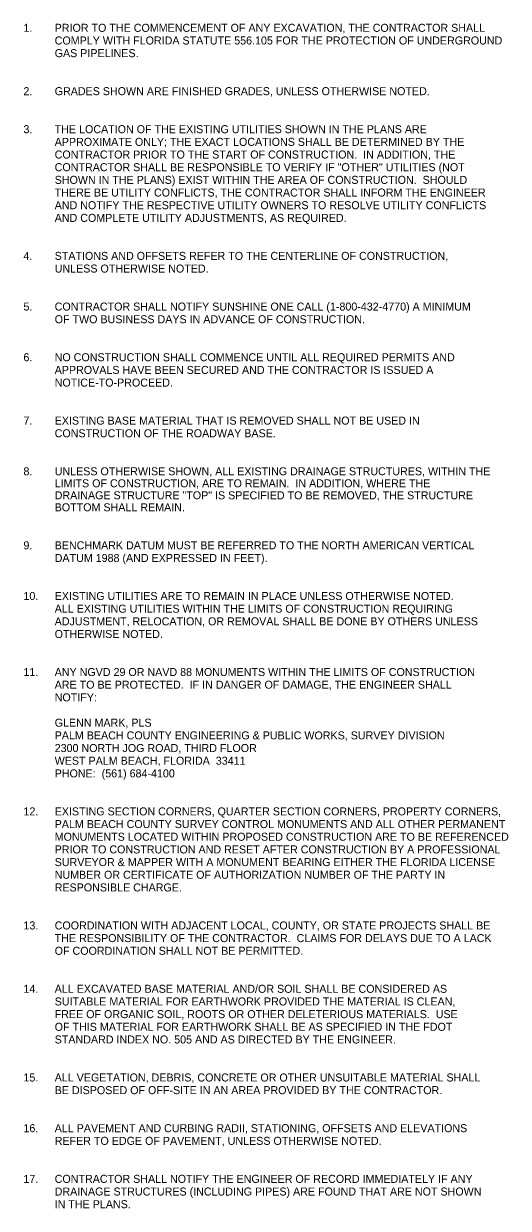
# Model space of a CAD drawing. Extents: x 783907 to 784590, y 832310 to 832609.
# Drawn here: x 784194.4 to 784230.7, y 832519 to 832607.8 of the extents above; entities that cross this region are included whole.
import ezdxf

# ---------------------------------------------------------------- set-up
doc = ezdxf.new("R2010")
doc.units = 0
doc.layers.add('Default', color=7, linetype='Continuous')

msp = doc.modelspace()

# ---------------------------------------------------------------- texts
at = {"layer": 'Default'}
for s, p in [('1.', (784194.352, 832607.22)), ('PRIOR TO THE COMMENCEMENT OF ANY EXCAVATION, THE CONTRACTOR SHALL ', (784196.695, 832607.22)), ('COMPLY WITH FLORIDA STATUTE 556.105 FOR THE PROTECTION OF UNDERGROUND', (784196.695, 832606.27)), ('GAS PIPELINES.', (784196.695, 832605.32)), ('2.', (784194.352, 832602.47)), ('GRADES SHOWN ARE FINISHED GRADES, UNLESS OTHERWISE NOTED.', (784196.695, 832602.47)), ('3.', (784194.352, 832599.62)), ('THE LOCATION OF THE EXISTING UTILITIES SHOWN IN THE PLANS ARE', (784196.695, 832599.62)), ('APPROXIMATE ONLY; THE EXACT LOCATIONS SHALL BE DETERMINED BY THE', (784196.695, 832598.67)), ('CONTRACTOR PRIOR TO THE START OF CONSTRUCTION.  IN ADDITION, THE', (784196.695, 832597.72)), ('CONTRACTOR SHALL BE RESPONSIBLE TO VERIFY IF "OTHER" UTILITIES (NOT', (784196.695, 832596.77)), ('SHOWN IN THE PLANS) EXIST WITHIN THE AREA OF CONSTRUCTION.  SHOULD', (784196.695, 832595.82)), ('THERE BE UTILITY CONFLICTS, THE CONTRACTOR SHALL INFORM THE ENGINEER', (784196.695, 832594.87)), ('AND NOTIFY THE RESPECTIVE UTILITY OWNERS TO RESOLVE UTILITY CONFLICTS', (784196.695, 832593.92)), ('AND COMPLETE UTILITY ADJUSTMENTS, AS REQUIRED.', (784196.695, 832592.97)), ('4.', (784194.352, 832590.12)), ('STATIONS AND OFFSETS REFER TO THE CENTERLINE OF CONSTRUCTION,', (784196.695, 832590.12)), ('UNLESS OTHERWISE NOTED.', (784196.695, 832589.17)), ('5.', (784194.352, 832586.32)), ('CONTRACTOR SHALL NOTIFY SUNSHINE ONE CALL (1-800-432-4770) A MINIMUM', (784196.695, 832586.32)), ('OF TWO BUSINESS DAYS IN ADVANCE OF CONSTRUCTION.', (784196.695, 832585.37)), ('6.', (784194.352, 832582.52)), ('NO CONSTRUCTION SHALL COMMENCE UNTIL ALL REQUIRED PERMITS AND ', (784196.695, 832582.52)), ('APPROVALS HAVE BEEN SECURED AND THE CONTRACTOR IS ISSUED A', (784196.695, 832581.57)), ('NOTICE-TO-PROCEED.', (784196.695, 832580.62)), ('7.', (784194.352, 832577.77)), ('EXISTING BASE MATERIAL THAT IS REMOVED SHALL NOT BE USED IN', (784196.695, 832577.77)), ('CONSTRUCTION OF THE ROADWAY BASE.', (784196.695, 832576.82)), ('8.', (784194.352, 832573.97)), ('UNLESS OTHERWISE SHOWN, ALL EXISTING DRAINAGE STRUCTURES, WITHIN THE', (784196.695, 832573.97)), ('LIMITS OF CONSTRUCTION, ARE TO REMAIN.  IN ADDITION, WHERE THE', (784196.695, 832573.07)), ('DRAINAGE STRUCTURE "TOP" IS SPECIFIED TO BE REMOVED, THE STRUCTURE', (784196.695, 832572.17)), ('BOTTOM SHALL REMAIN.', (784196.695, 832571.27)), ('9.', (784194.352, 832568.42)), ('BENCHMARK DATUM MUST BE REFERRED TO THE NORTH AMERICAN VERTICAL', (784196.695, 832568.42)), ('DATUM 1988 (AND EXPRESSED IN FEET).', (784196.695, 832567.47)), ('10.', (784194.352, 832564.62)), ('EXISTING UTILITIES ARE TO REMAIN IN PLACE UNLESS OTHERWISE NOTED.  ', (784196.695, 832564.62)), ('ALL EXISTING UTILITIES WITHIN THE LIMITS OF CONSTRUCTION REQUIRING', (784196.695, 832563.67)), ('ADJUSTMENT, RELOCATION, OR REMOVAL SHALL BE DONE BY OTHERS UNLESS', (784196.695, 832562.72)), ('OTHERWISE NOTED.', (784196.695, 832561.77)), ('11.', (784194.352, 832558.92)), ('ANY NGVD 29 OR NAVD 88 MONUMENTS WITHIN THE LIMITS OF CONSTRUCTION ', (784196.695, 832558.92)), ('ARE TO BE PROTECTED.  IF IN DANGER OF DAMAGE, THE ENGINEER SHALL ', (784196.695, 832557.97)), ('NOTIFY:', (784196.695, 832557.02)), ('GLENN MARK, PLS', (784196.695, 832555.12)), ('PALM BEACH COUNTY ENGINEERING & PUBLIC WORKS, SURVEY DIVISION', (784196.695, 832554.17)), ('2300 NORTH JOG ROAD, THIRD FLOOR ', (784196.695, 832553.22)), ('WEST PALM BEACH, FLORIDA  33411', (784196.695, 832552.27)), ('PHONE:  (561) 684-4100', (784196.695, 832551.32)), ('12.', (784194.352, 832548.47)), ('EXISTING SECTION CORNERS, QUARTER SECTION CORNERS, PROPERTY CORNERS,', (784196.695, 832548.47)), ('PALM BEACH COUNTY SURVEY CONTROL MONUMENTS AND ALL OTHER PERMANENT', (784196.695, 832547.52)), ('MONUMENTS LOCATED WITHIN PROPOSED CONSTRUCTION ARE TO BE REFERENCED', (784196.695, 832546.57)), ('PRIOR TO CONSTRUCTION AND RESET AFTER CONSTRUCTION BY A PROFESSIONAL', (784196.695, 832545.62)), ('SURVEYOR & MAPPER WITH A MONUMENT BEARING EITHER THE FLORIDA LICENSE', (784196.695, 832544.67)), ('NUMBER OR CERTIFICATE OF AUTHORIZATION NUMBER OF THE PARTY IN', (784196.695, 832543.72)), ('RESPONSIBLE CHARGE.', (784196.695, 832542.77)), ('13.', (784194.352, 832539.92)), ('COORDINATION WITH ADJACENT LOCAL, COUNTY, OR STATE PROJECTS SHALL BE', (784196.695, 832539.92)), ('THE RESPONSIBILITY OF THE CONTRACTOR.  CLAIMS FOR DELAYS DUE TO A LACK ', (784196.695, 832538.97)), ('OF COORDINATION SHALL NOT BE PERMITTED.', (784196.695, 832538.02)), ('14.', (784194.352, 832535.17)), ('ALL EXCAVATED BASE MATERIAL AND/OR SOIL SHALL BE CONSIDERED AS ', (784196.695, 832535.17)), ('SUITABLE MATERIAL FOR EARTHWORK PROVIDED THE MATERIAL IS CLEAN, ', (784196.695, 832534.22)), ('FREE OF ORGANIC SOIL, ROOTS OR OTHER DELETERIOUS MATERIALS.  USE ', (784196.695, 832533.27)), ('OF THIS MATERIAL FOR EARTHWORK SHALL BE AS SPECIFIED IN THE FDOT ', (784196.695, 832532.32)), ('STANDARD INDEX NO. 505 AND AS DIRECTED BY THE ENGINEER.', (784196.695, 832531.37)), ('15.', (784194.352, 832528.52)), ('ALL VEGETATION, DEBRIS, CONCRETE OR OTHER UNSUITABLE MATERIAL SHALL ', (784196.695, 832528.52)), ('BE DISPOSED OF OFF-SITE IN AN AREA PROVIDED BY THE CONTRACTOR.', (784196.695, 832527.57)), ('16.', (784194.352, 832524.72)), ('ALL PAVEMENT AND CURBING RADII, STATIONING, OFFSETS AND ELEVATIONS ', (784196.695, 832524.72)), ('REFER TO EDGE OF PAVEMENT, UNLESS OTHERWISE NOTED.', (784196.695, 832523.77)), ('17.', (784194.352, 832520.92)), ('CONTRACTOR SHALL NOTIFY THE ENGINEER OF RECORD IMMEDIATELY IF ANY', (784196.695, 832520.92)), ('DRAINAGE STRUCTURES (INCLUDING PIPES) ARE FOUND THAT ARE NOT SHOWN', (784196.695, 832519.97)), ('IN THE PLANS.', (784196.695, 832519.02))]:
    msp.add_text(s, height=0.6, dxfattribs=at).set_placement(p)

doc.saveas('drawing.dxf')
